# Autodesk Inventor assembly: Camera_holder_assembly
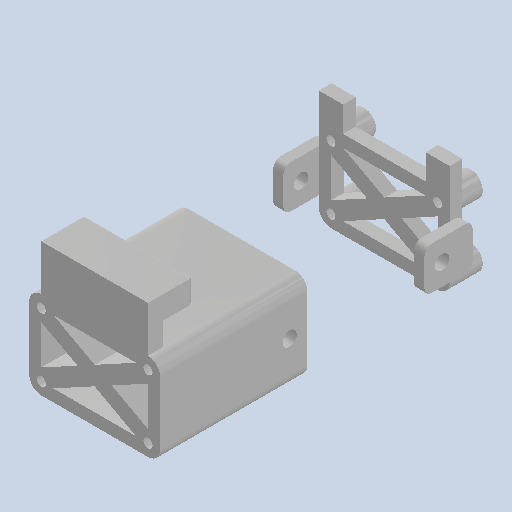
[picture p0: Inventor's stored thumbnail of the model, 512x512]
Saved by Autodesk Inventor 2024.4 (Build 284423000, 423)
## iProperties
Created: 2025-07
Part Number: Camera_holder_assembly
Document SubType Name: Assembly
Designer: AdminForWorker
Title: Camera_holder_assembly v3
Author: AdminForWorker
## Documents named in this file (3)
- c:\worker\convert-fusion-r03-cosv3\tmp\job-1\5\temp\files\5ff960f3-d26c-4098-881d-fd8d4ea677f4\b6146b7f-86f5-47fa-81a0-a429fdf79268.iam
- c:\worker\convert-fusion-r03-cosv3\tmp\job-1\5\temp\files\5ff960f3-d26c-4098-881d-fd8d4ea677f4\Component1.ipt
- c:\worker\convert-fusion-r03-cosv3\tmp\job-1\5\temp\files\5ff960f3-d26c-4098-881d-fd8d4ea677f4\Component2.ipt
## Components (2 placed, 2 different names)
1. Component1:1
2. Component2:1
